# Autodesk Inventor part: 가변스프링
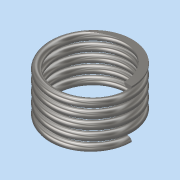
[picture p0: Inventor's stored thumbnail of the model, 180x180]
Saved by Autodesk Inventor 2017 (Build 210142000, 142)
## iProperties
Part Number: 가변스프링
Material: 스테인레스 스틸
Document SubType Name: Modeling
Designer: mrc
Density: 8 g/cm^3
Appearance: 반연마
Mass: 7.63156 g
Surface Area: 19.566 cm^2
Volume: 0.953945 cm^3
Author: mrc
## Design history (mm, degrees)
sketch "스케치1"
  geometry: L1 (0, 0)-(10, 0); L2 (10, 0)-(10, 12.7); L3 (10, 12.7)-(0, 12.7); L4 (0, 12.7)-(0, 0); C1 r 1 at (10, 0)
  constraints: 8 end point, 2 parallel, 1 centre point, 1 coincident, 1 horizontal, 1 perpendicular
  dimensions: "d0" = 2 diameter of C1; "d1" = 12.7 distance of L3.end L1.start (derived); "d2" = 20 diameter of L2 L4
feature "코일1" sketch "스케치1" pitch "d3" = 10; turns "d5" = 5; dims "d4" = 12.7 (= d1), "d6" = 0, angle "d7" = 90 deg, angle "d8" = 90 deg, "d9" = 0, "d10" = 0
sketch "스케치2"
  geometry: L1 (-15, 12.7)-(35, 12.7); L2 (35, 12.7)-(35, 0); L3 (35, 0)-(-15, 0); L4 (-15, 0)-(-15, 12.7); C1 r 1 at (10, 0) reference; 5 further points
  constraints: 8 end point, 2 coincident, 2 midpoint, 2 parallel, 1 horizontal, 1 horizontal alignment, 1 perpendicular
  dimensions: "d11" = 50 distance of L1.start L1.end
extrude "돌출1" sketch "스케치2" stored distance "d12" = 0; taper "d13" = 0 deg
node "솔리드1"
